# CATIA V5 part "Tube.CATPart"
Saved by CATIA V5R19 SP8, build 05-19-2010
Part number: Tube
Publications: "Rayon_trou"
Bounding box of the stored display mesh (mm): x -50 to 50, y -50 to 50, z 0 to 50
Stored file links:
  F:\! CONCEPTION\PROJET\Mécanisme 11\CAO\Tube.CATPart
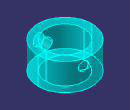
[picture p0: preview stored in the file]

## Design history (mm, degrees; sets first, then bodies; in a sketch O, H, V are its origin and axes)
Parameters
  Rayon_trou = 10 mm
Body1 (main body)
  Sketch1 on xy-plane, origin (0, 0, 0), H (1, 0, 0), V (0, 1, 0)
    circle A1 centre (0, 0) radius 50
    circle A2 centre (0, 0) radius 35
    radius A2 = 35
    radius A1 = 50
  Pad1: profile Sketch1, direction (0, 0, 1), length 50
  Sketch2 on zx-plane, origin (0, 0, 0), H (-1, 0, 0), V (0, 0, 1)
    circle A1 centre (0, 25) radius 10
    point P1 (0, 25)
    distance P1 H = 25
    radius A1 = 10 {= Rayon_trou}
    coincidence: P1 V
  Pocket1: profile Sketch2, direction (0, -1, 0), through (limit type 3)
  Plane1: type Offset, RefPlane xy-plane, Offset 25
  Sketch3 on Plane1, origin (0, 0, 25), H (1, 0, 0), V (0, 1, 0)
    line L1 (0, 33) -> (0, 43)
    line L2 (0, 43) -> (10, 33)
    line L3 (10, 33) -> (0, 33)
    length L1 = 10 {= Rayon_trou}
    length L3 = 10 {= Rayon_trou}
    distance L3 H = 33
    vertical: L1 V
    horizontal: L3 H
    coincidence: L1 V
  Groove1: profile Sketch3, axis Sketch3.V, angle 360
